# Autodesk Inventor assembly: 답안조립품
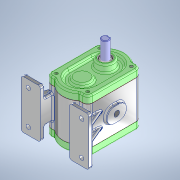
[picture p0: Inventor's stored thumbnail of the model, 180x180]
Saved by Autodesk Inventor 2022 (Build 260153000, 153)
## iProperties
Created: 2023-06
Part Number: 답안조립품
Document SubType Name: Assembly
Designer: PC-01
Author: PC-01
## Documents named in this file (12)
- C:\Users\PC-01\Desktop\730606V1015\답안조립품.iam
- C:\Users\PC-01\Desktop\730606V1015\본체.ipt
- C:\Users\PC-01\Desktop\730606V1015\샤프트.ipt
- C:\Users\PC-01\Desktop\730606V1015\묻힘키 6x6x40.ipt
- C:\Users\PC-01\Desktop\730606V1015\니들베어링 NA 4902.ipt
- C:\Users\PC-01\Desktop\730606V1015\서브 드라이브 기어.ipt
- C:\Users\PC-01\Desktop\730606V1015\메인 드라이브 기어.ipt
- C:\Users\PC-01\Desktop\730606V1015\뒷커버.ipt
- C:\Users\PC-01\Desktop\730606V1015\앞커버.ipt
- C:\Users\PC-01\Desktop\730606V1015\오일실 15 25 7.ipt
- C:\Users\PC-01\Desktop\730606V1015\가스켓.ipt
- C:\Users\PC-01\Desktop\730606V1015\육각 소켓 머리 볼트 M8 x 100.ipt
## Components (2 placed, 1 different names)
1. 가스켓:1
2. 가스켓:2
